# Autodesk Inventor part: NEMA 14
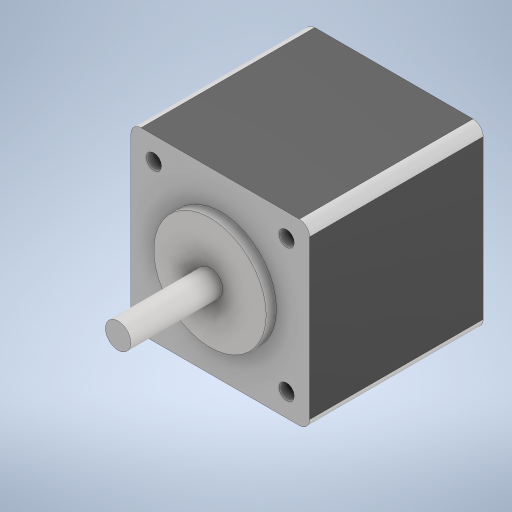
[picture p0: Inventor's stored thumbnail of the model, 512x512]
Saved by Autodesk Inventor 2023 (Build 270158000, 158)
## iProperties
Created: 2025-07
Part Number: NEMA 14
Material: Generic
Document SubType Name: Modeling
Designer: erjon
Density: 1 g/cm^3
Appearance: Default
Author: erjon
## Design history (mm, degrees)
feature "Base1"
body "Solid1"
